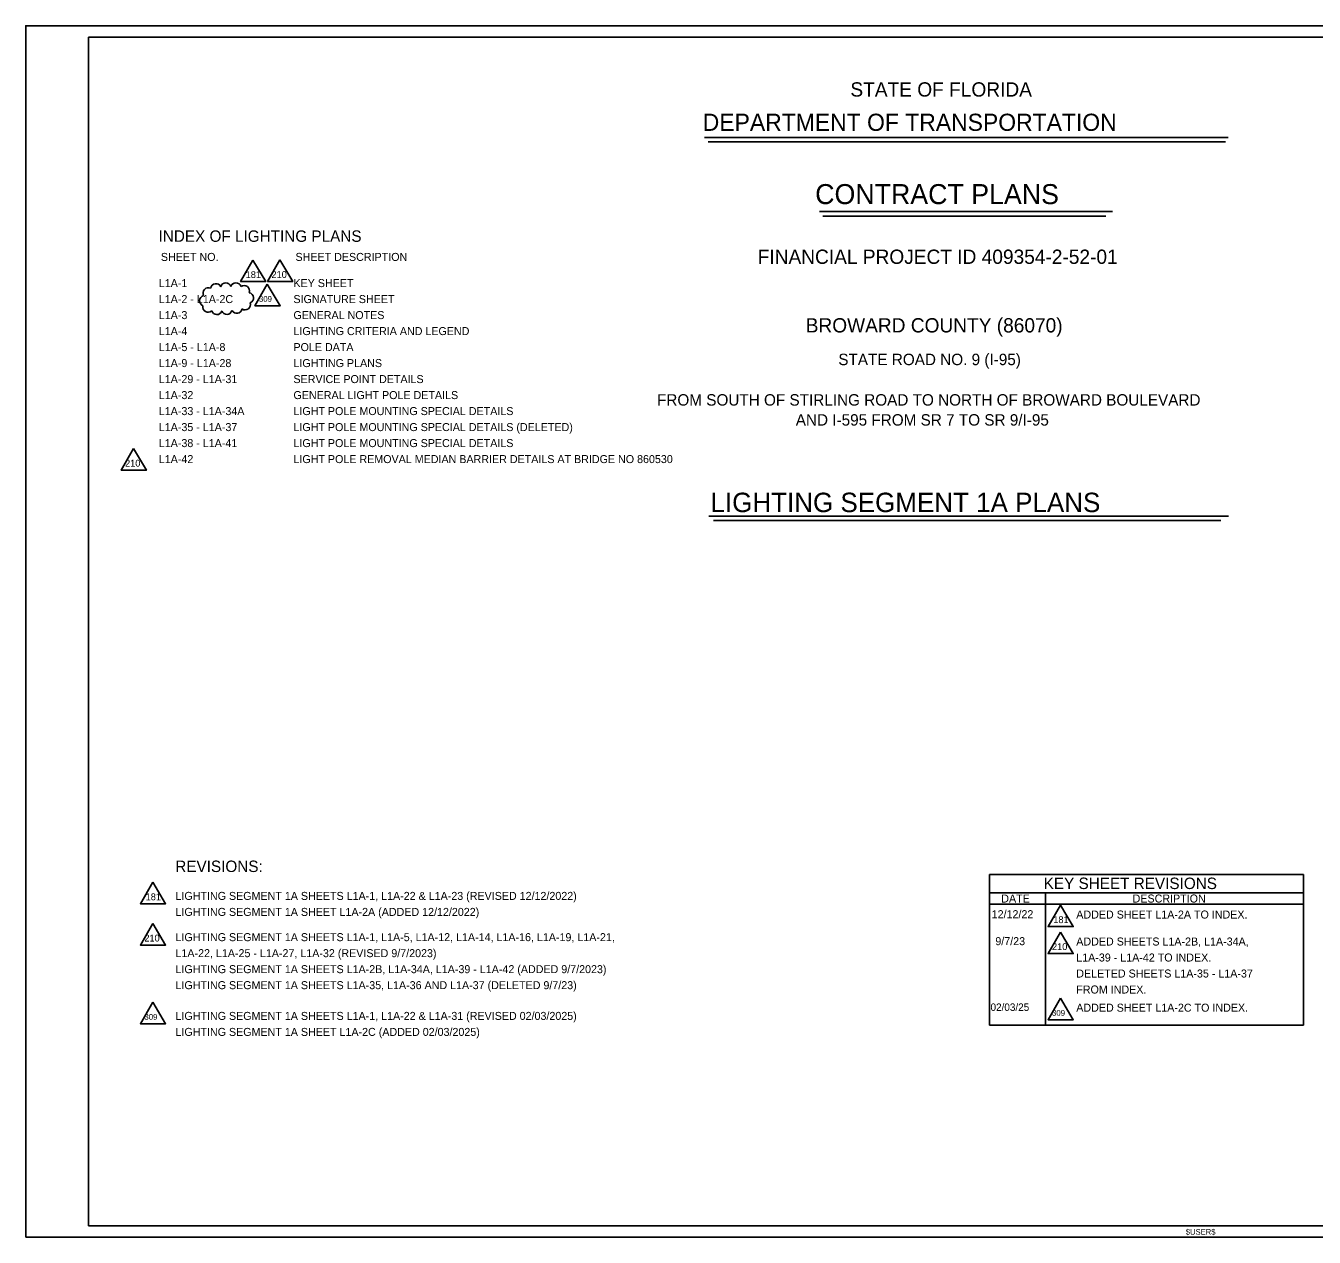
# Model space of a CAD drawing. Extents: x -820.2 to -798.1, y -2199.1 to -2182.2.
# Drawn here: x -820.23 to -808.95, y -2199.12 to -2188.52 of the extents above; entities that cross this region are included whole.
import ezdxf

# ---------------------------------------------------------------- set-up
doc = ezdxf.new("R2010")
doc.units = 0
for name, color, linetype in [('AdhocPoint_dp', 7, 'Continuous'), ('Cloud_dp', 7, 'Continuous'), ('PlotBorder_dp', 7, 'Continuous'), ('SheetBorder_dp', 7, 'Continuous'), ('SumBoxLines_dp', 7, 'Continuous'), ('TextLabel', 7, 'Continuous'), ('TextMinor', 7, 'Continuous'), ('TextNotes', 7, 'Continuous'), ('TextTitle', 7, 'Continuous')]:
    doc.layers.add(name, color=color, linetype=linetype)

msp = doc.modelspace()

# ---------------------------------------------------------------- linework, layer by layer
at = {"layer": 'AdhocPoint_dp'}
msp.add_line((-820.227, -2199.124), (-820.227, -2199.124), dxfattribs=at)
at = {"layer": 'Cloud_dp'}
for points in [[(-818.24, -2190.573), (-818.348, -2190.761), (-818.127, -2190.761)], [(-818.004, -2190.572), (-818.111, -2190.76), (-817.891, -2190.76)], [(-818.114, -2190.785), (-818.222, -2190.973), (-818.001, -2190.973)], [(-819.284, -2192.223), (-819.392, -2192.412), (-819.171, -2192.412)], [(-819.116, -2196.017), (-819.224, -2196.205), (-819.003, -2196.205)], [(-811.175, -2196.217), (-811.283, -2196.405), (-811.062, -2196.405)], [(-819.116, -2196.378), (-819.224, -2196.567), (-819.003, -2196.567)], [(-811.175, -2196.453), (-811.283, -2196.641), (-811.062, -2196.641)], [(-819.116, -2197.068), (-819.224, -2197.256), (-819.003, -2197.256)], [(-811.175, -2197.032), (-811.283, -2197.22), (-811.062, -2197.22)]]:
    msp.add_lwpolyline(points, close=True, dxfattribs=at)
for centre, start, end in [((-818.563, -2190.827), 25.9096, 170.9096), ((-818.477, -2190.82), 18.5195, 163.5195), ((-818.388, -2190.819), 17.5, 162.5), ((-818.66, -2190.93), 103.3617, 248.3617), ((-818.63, -2190.862), 63.7763, 208.7763), ((-818.316, -2190.843), 340.504, 125.504), ((-818.281, -2190.905), 293.5283, 78.5283), ((-818.632, -2190.983), 167.6812, 312.6812), ((-818.468, -2191.003), 201.1358, 346.1358), ((-818.38, -2190.993), 205.9222, 350.9222), ((-818.307, -2190.963), 234.2456, 19.2456), ((-818.555, -2191.004), 196.176, 341.176)]:
    msp.add_arc(centre, 0.0467, start, end, dxfattribs=at)
at = {"layer": 'PlotBorder_dp'}
msp.add_lwpolyline([(-820.227, -2199.124), (-803.727, -2199.124), (-803.727, -2188.524), (-820.227, -2188.524)], close=True, dxfattribs=at)
at = {"layer": 'SheetBorder_dp'}
for p, q in [((-819.677, -2188.624), (-819.677, -2199.024)), ((-819.677, -2188.624), (-804.277, -2188.624)), ((-819.677, -2199.024), (-804.277, -2199.024))]:
    msp.add_line(p, q, dxfattribs=at)
at = {"layer": 'SumBoxLines_dp'}
for p, q in [((-811.796, -2195.95), (-811.796, -2197.269)), ((-811.796, -2195.95), (-809.048, -2195.95)), ((-809.048, -2195.95), (-809.048, -2197.269)), ((-811.796, -2196.11), (-809.048, -2196.11)), ((-811.306, -2196.11), (-811.306, -2197.269)), ((-811.796, -2196.21), (-809.048, -2196.21)), ((-811.796, -2197.269), (-809.048, -2197.269))]:
    msp.add_line(p, q, dxfattribs=at)
at = {"layer": 'TextTitle'}
for p, q in [((-814.289, -2189.5), (-809.707, -2189.5)), ((-814.257, -2189.538), (-809.729, -2189.538)), ((-813.281, -2190.15), (-810.719, -2190.15)), ((-813.253, -2190.188), (-810.777, -2190.188)), ((-814.252, -2192.813), (-809.704, -2192.813)), ((-814.209, -2192.851), (-809.772, -2192.851))]:
    msp.add_line(p, q, dxfattribs=at)

# ---------------------------------------------------------------- texts
at = {"layer": 'Cloud_dp'}
for s, height, p in [('181', 0.06, (-818.303, -2190.731)), ('210', 0.06, (-818.077, -2190.73)), ('309', 0.051, (-818.187, -2190.939)), ('210', 0.06, (-819.358, -2192.381)), ('181', 0.06, (-819.178, -2196.175)), ('181', 0.06, (-811.237, -2196.375)), ('210', 0.06, (-819.189, -2196.536)), ('210', 0.06, (-811.248, -2196.611)), ('309', 0.051, (-819.189, -2197.221)), ('309', 0.051, (-811.248, -2197.186))]:
    msp.add_text(s, height=height, rotation=0, dxfattribs=at).set_placement(p)
at = {"layer": 'TextLabel'}
for s, height, p in [('INDEX OF LIGHTING PLANS', 0.1, (-819.065, -2190.414)), ('FINANCIAL PROJECT ID 409354-2-52-01', 0.125, (-813.823, -2190.607)), ('L1A-1', 0.07, (-819.063, -2190.81)), ('KEY SHEET', 0.07, (-817.885, -2190.81)), ('L1A-2 - L1A-2C', 0.07, (-819.063, -2190.95)), ('SIGNATURE SHEET', 0.07, (-817.885, -2190.95)), ('L1A-3', 0.07, (-819.063, -2191.09)), ('GENERAL NOTES', 0.07, (-817.885, -2191.09)), ('BROWARD COUNTY (86070)', 0.125, (-813.403, -2191.207)), ('L1A-4', 0.07, (-819.063, -2191.23)), ('LIGHTING CRITERIA AND LEGEND', 0.07, (-817.885, -2191.23)), ('L1A-5 - L1A-8', 0.07, (-819.063, -2191.37)), ('POLE DATA', 0.07, (-817.885, -2191.37)), ('L1A-9 - L1A-28', 0.07, (-819.063, -2191.51)), ('LIGHTING PLANS', 0.07, (-817.885, -2191.51)), ('STATE ROAD NO. 9 (I-95)', 0.1, (-813.118, -2191.493)), ('L1A-29 - L1A-31', 0.07, (-819.063, -2191.65)), ('SERVICE POINT DETAILS', 0.07, (-817.885, -2191.65)), ('L1A-32', 0.07, (-819.063, -2191.79)), ('GENERAL LIGHT POLE DETAILS', 0.07, (-817.885, -2191.79)), ('FROM SOUTH OF STIRLING ROAD TO NORTH OF BROWARD BOULEVARD', 0.1, (-814.704, -2191.847)), ('L1A-33 - L1A-34A', 0.07, (-819.063, -2191.93)), ('LIGHT POLE MOUNTING SPECIAL DETAILS', 0.07, (-817.885, -2191.93)), ('L1A-35 - L1A-37', 0.07, (-819.063, -2192.07)), ('LIGHT POLE MOUNTING SPECIAL DETAILS (DELETED)', 0.07, (-817.885, -2192.07)), ('AND I-595 FROM SR 7 TO SR 9/I-95', 0.1, (-813.49, -2192.022)), ('L1A-38 - L1A-41', 0.07, (-819.063, -2192.21)), ('LIGHT POLE MOUNTING SPECIAL DETAILS', 0.07, (-817.885, -2192.21)), ('L1A-42', 0.07, (-819.063, -2192.35)), ('LIGHT POLE REMOVAL MEDIAN BARRIER DETAILS AT BRIDGE NO 860530', 0.07, (-817.885, -2192.35)), ('REVISIONS:', 0.1, (-818.919, -2195.928)), ('KEY SHEET REVISIONS', 0.1, (-811.321, -2196.077))]:
    msp.add_text(s, height=height, dxfattribs=at).set_placement(p)
at = {"layer": 'TextMinor'}
for s, height, p in [('12/12/22', 0.07, (-811.776, -2196.332)), ('ADDED SHEET L1A-2A TO INDEX.', 0.07, (-811.036, -2196.335)), ('9/7/23', 0.07, (-811.744, -2196.568)), ('ADDED SHEETS L1A-2B, L1A-34A, ', 0.07, (-811.036, -2196.571)), ('L1A-39 - L1A-42 TO INDEX.', 0.07, (-811.036, -2196.711)), ('DELETED SHEETS L1A-35 - L1A-37 ', 0.07, (-811.036, -2196.851)), ('FROM INDEX.', 0.07, (-811.036, -2196.991)), ('02/03/25', 0.065, (-811.786, -2197.143)), ('ADDED SHEET L1A-2C TO INDEX.', 0.07, (-811.036, -2197.15)), ('$USER$', 0.05, (-810.078, -2199.102))]:
    msp.add_text(s, height=height, dxfattribs=at).set_placement(p)
at = {"layer": 'TextNotes'}
for s, height, p in [('SHEET NO.', 0.07, (-819.045, -2190.581)), ('SHEET DESCRIPTION', 0.07, (-817.867, -2190.581)), ('LIGHTING SEGMENT 1A SHEETS L1A-1, L1A-22 & L1A-23 (REVISED 12/12/2022)', 0.06998, (-818.917, -2196.172)), ('DATE', 0.07, (-811.692, -2196.195)), ('DESCRIPTION', 0.07, (-810.543, -2196.195)), ('LIGHTING SEGMENT 1A SHEET L1A-2A (ADDED 12/12/2022)', 0.06998, (-818.917, -2196.312)), ('LIGHTING SEGMENT 1A SHEETS L1A-1, L1A-5, L1A-12, L1A-14, L1A-16, L1A-19, L1A-21, ', 0.06998, (-818.917, -2196.533)), ('L1A-22, L1A-25 - L1A-27, L1A-32 (REVISED 9/7/2023)', 0.06998, (-818.917, -2196.673)), ('LIGHTING SEGMENT 1A SHEETS L1A-2B, L1A-34A, L1A-39 - L1A-42 (ADDED 9/7/2023)', 0.06998, (-818.917, -2196.813)), ('LIGHTING SEGMENT 1A SHEETS L1A-35, L1A-36 AND L1A-37 (DELETED 9/7/23)', 0.06998, (-818.917, -2196.953)), ('LIGHTING SEGMENT 1A SHEETS L1A-1, L1A-22 & L1A-31 (REVISED 02/03/2025)', 0.06998, (-818.917, -2197.222)), ('LIGHTING SEGMENT 1A SHEET L1A-2C (ADDED 02/03/2025)', 0.06998, (-818.917, -2197.362))]:
    msp.add_text(s, height=height, dxfattribs=at).set_placement(p)
at = {"layer": 'TextTitle'}
for s, height, p in [('STATE OF FLORIDA', 0.125, (-813.012, -2189.143)), ('DEPARTMENT OF TRANSPORTATION', 0.15, (-814.304, -2189.443)), ('CONTRACT PLANS', 0.175, (-813.32, -2190.084)), ('LIGHTING SEGMENT 1A PLANS', 0.17, (-814.236, -2192.779))]:
    msp.add_text(s, height=height, dxfattribs=at).set_placement(p)

doc.saveas('drawing.dxf')
